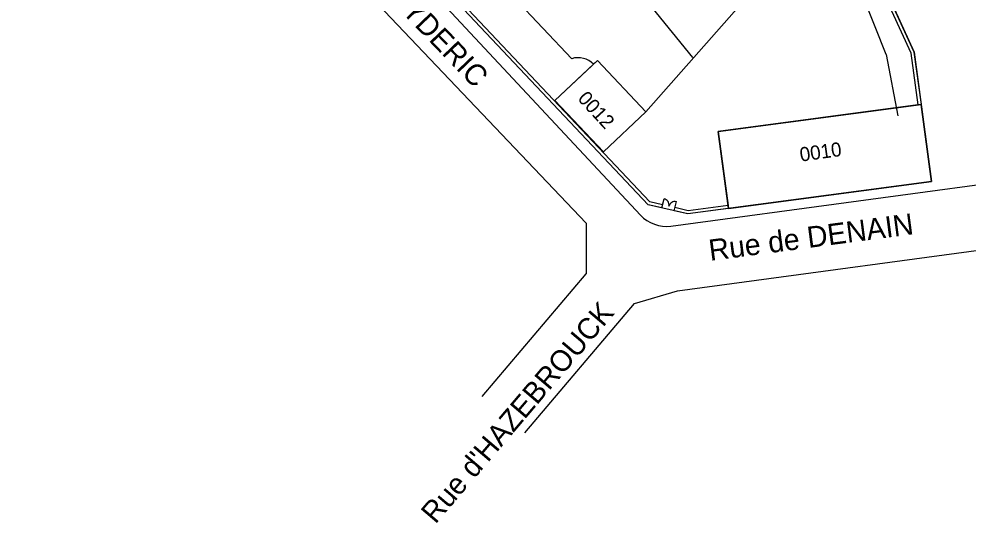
# Model space of a CAD drawing. Extents: x 703432 to 707394, y 7057985 to 7059523.
# Drawn here: x 704177.7 to 704312.2, y 7058656.8 to 7058728.3 of the extents above; entities that cross this region are included whole.
import ezdxf

# ---------------------------------------------------------------- set-up
doc = ezdxf.new("R2010")
doc.units = 0
for name, color, linetype in [('DH_HACHURE-MOTIF', 7, 'Continuous'), ('DH_TEXTE', 7, 'Continuous'), ('GO_MUR_EXTERIEUR', 7, 'Continuous'), ('IMM_LIMITE PHYSIQUE', 7, 'Continuous'), ('R_EPR_AEP_CANALISATION_CL_A', 7, 'Continuous'), ('SID_NUMERO_BATI', 7, 'Continuous'), ('SID_POLYLIGNES_BATI', 7, 'Continuous'), ('SID_POLYLIGNES_IMMEUBLE', 7, 'Continuous'), ('VOIRIE_BORDURE', 7, 'Continuous'), ('VOIRIE_ROUTE', 7, 'Continuous')]:
    doc.layers.add(name, color=color, linetype=linetype)

msp = doc.modelspace()

# ---------------------------------------------------------------- linework, layer by layer
at = {"layer": 'DH_HACHURE-MOTIF'}
for points in [[(704259.13, 7058721.87), (704253.66, 7058716.72), (704260.53, 7058709.44), (704266.57, 7058715.15), (704259.71, 7058722.42), (704259.13, 7058721.87)], [(704278.22, 7058701.86), (704278.28, 7058701.42), (704307.02, 7058705.27), (704305.56, 7058716.18), (704305.11, 7058716.12), (704276.81, 7058712.32), (704278.22, 7058701.86)]]:
    msp.add_lwpolyline(points, dxfattribs=at)
at = {"layer": 'GO_MUR_EXTERIEUR'}
for p, q in [((704253.66, 7058716.72), (704259.71, 7058722.42)), ((704259.71, 7058722.42), (704266.57, 7058715.15)), ((704260.53, 7058709.44), (704253.66, 7058716.72)), ((704276.81, 7058712.32), (704305.56, 7058716.18)), ((704305.56, 7058716.18), (704307.02, 7058705.27)), ((704266.57, 7058715.15), (704260.53, 7058709.44)), ((704278.28, 7058701.42), (704276.81, 7058712.32)), ((704307.02, 7058705.27), (704278.28, 7058701.42))]:
    msp.add_line(p, q, dxfattribs=at)
at = {"layer": 'IMM_LIMITE PHYSIQUE'}
for p, q in [((704203.2, 7058769.48), (704266.9, 7058701.96)), ((704203.53, 7058769.79), (704267.13, 7058702.37)), ((704268.83, 7058701.51), (704269.13, 7058702.8)), ((704268.83, 7058701.51), (704266.9, 7058701.96)), ((704268.93, 7058701.95), (704267.13, 7058702.37)), ((704270.58, 7058701.1), (704270.88, 7058702.39)), ((704272.53, 7058701.1), (704270.68, 7058701.54)), ((704278.28, 7058701.42), (704272.51, 7058700.64)), ((704278.22, 7058701.86), (704272.53, 7058701.1)), ((704272.51, 7058700.64), (704270.58, 7058701.1))]:
    msp.add_line(p, q, dxfattribs=at)
for points in [[(704305.17, 7058716.12), (704304.14, 7058723.47), (704296.24, 7058740.75)], [(704305.62, 7058716.18), (704304.58, 7058723.59), (704296.65, 7058740.93)]]:
    msp.add_lwpolyline(points, dxfattribs=at)
for centre, start, end in [((704268.96, 7058701.94), 346.7916, 78.7098), ((704270.66, 7058701.54), 75.2683, 166.7916)]:
    msp.add_arc(centre, 0.874, start, end, dxfattribs=at)
at = {"layer": 'R_EPR_AEP_CANALISATION_CL_A'}
for p, q in [((704266.57, 7058715.15), (704298.24, 7058751.07)), ((704300.63, 7058723.25), (704292.51, 7058743.82)), ((704300.63, 7058723.25), (704302.29, 7058714.54))]:
    msp.add_line(p, q, dxfattribs=at)
msp.add_lwpolyline([(704218.29, 7058779.15), (704227.29, 7058771.34), (704232.63, 7058772.76), (704273.17, 7058722.82)], dxfattribs=at)
at = {"layer": 'SID_POLYLIGNES_BATI'}
for p, q in [((704253.66, 7058716.72), (704259.71, 7058722.42)), ((704259.71, 7058722.42), (704266.57, 7058715.15)), ((704260.53, 7058709.44), (704253.66, 7058716.72)), ((704276.81, 7058712.32), (704305.56, 7058716.18)), ((704305.56, 7058716.18), (704307.02, 7058705.27)), ((704266.57, 7058715.15), (704260.53, 7058709.44)), ((704278.28, 7058701.42), (704276.81, 7058712.32)), ((704307.02, 7058705.27), (704278.28, 7058701.42))]:
    msp.add_line(p, q, dxfattribs=at)
at = {"layer": 'SID_POLYLIGNES_IMMEUBLE'}
for p, q in [((704266.9, 7058701.96), (704177.69, 7058796.52)), ((704296.65, 7058740.93), (704304.58, 7058723.59)), ((704304.58, 7058723.59), (704307.02, 7058705.27))]:
    msp.add_line(p, q, dxfattribs=at)
msp.add_lwpolyline([(704307.02, 7058705.27), (704272.51, 7058700.64), (704266.9, 7058701.96)], dxfattribs=at)
at = {"layer": 'VOIRIE_BORDURE'}
msp.add_line((704245.77, 7058733.56), (704256.04, 7058722.67), dxfattribs=at)
msp.add_arc((704256.95, 7058719.81), 3, 43.3308, 107.6513, dxfattribs=at)
at = {"layer": 'VOIRIE_ROUTE'}
for p, q in [((704258.1, 7058699.36), (704201.39, 7058759.02)), ((704213.46, 7058756.55), (704265.78, 7058700.48)), ((704258.1, 7058699.36), (704258.07, 7058692.14)), ((704243.33, 7058674.76), (704258.07, 7058692.14))]:
    msp.add_line(p, q, dxfattribs=at)
for points in [[(704270.1, 7058698.93), (704323.3, 7058706.08)], [(704249.41, 7058669.61), (704264.96, 7058687.96), (704271.02, 7058689.76), (704323.54, 7058696.82)]]:
    msp.add_lwpolyline(points, dxfattribs=at)
msp.add_arc((704269.44, 7058703.89), 5, 223.0213, 277.6524, dxfattribs=at)

# ---------------------------------------------------------------- texts
at = {"layer": 'DH_TEXTE'}
for s, rotation, p in [('Rue LYDERIC', 313.8024, (704224.4, 7058737.04)), ('Rue de DENAIN', 7.4746, (704275.67, 7058693.99)), ("Rue d'HAZEBROUCK", 49.6268, (704236.72, 7058656.56))]:
    msp.add_text(s, height=3, rotation=rotation, dxfattribs=at).set_placement(p)
at = {"layer": 'SID_NUMERO_BATI'}
for s, rotation, p in [('0012', 312.5129, (704256.78, 7058716.93)), ('0010', 8.0003, (704288.51, 7058708.06))]:
    msp.add_text(s, height=2, rotation=rotation, dxfattribs=at).set_placement(p)

doc.saveas('drawing.dxf')
